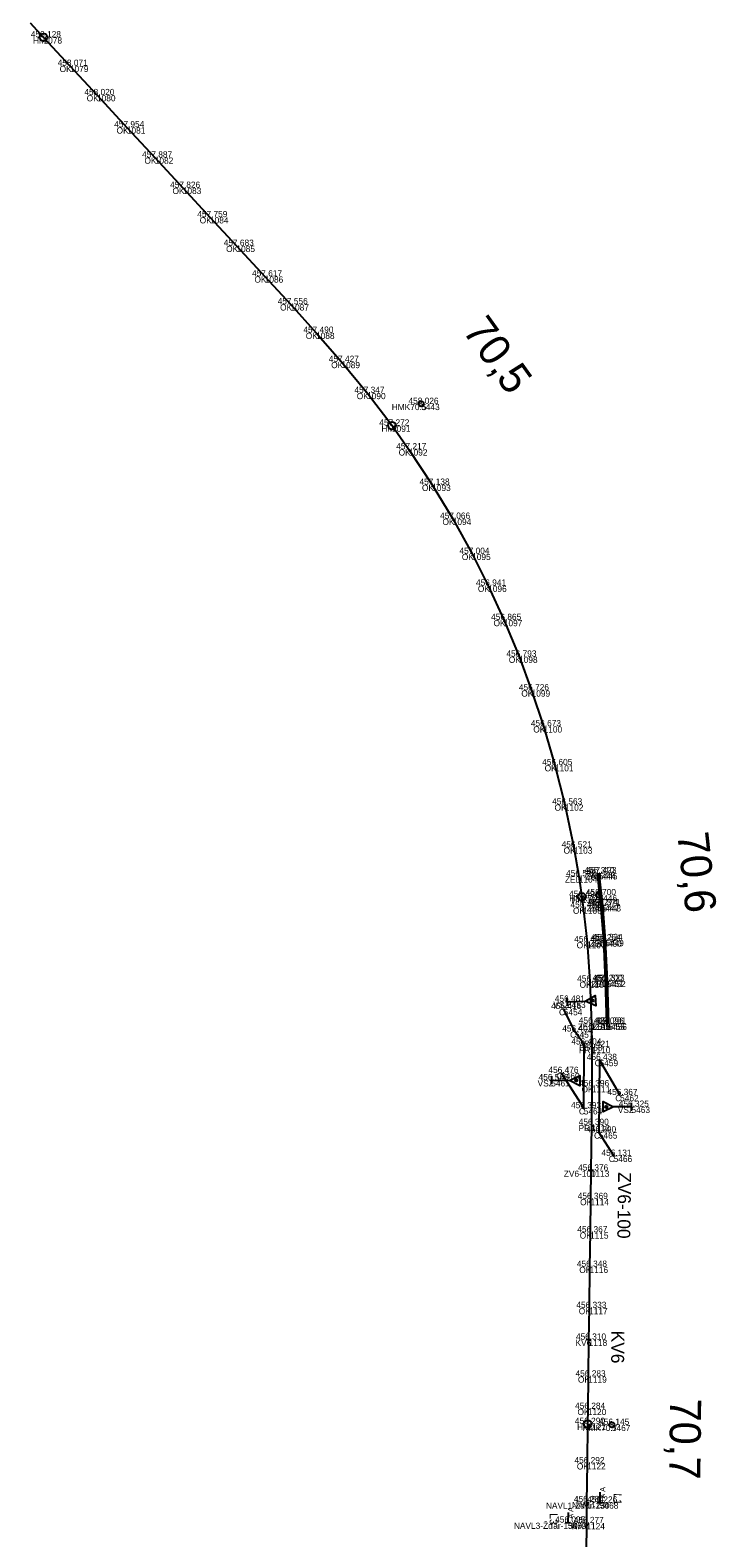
# Model space of a CAD drawing. Extents: x -621782 to -610392, y -1141853 to -1122321.
# Drawn here: x -621070.5 to -620938.2, y -1127142.3 to -1126851.5 of the extents above; entities that cross this region are included whole.
import ezdxf

# ---------------------------------------------------------------- set-up
doc = ezdxf.new("R2010")
doc.units = 0
for name, color, linetype in [('Vrstva 1', 7, 'Continuous'), ('Vrstva 13', 7, 'Continuous'), ('Vrstva 17', 7, 'Continuous'), ('Vrstva 2', 7, 'Continuous'), ('Vrstva 4', 7, 'Continuous'), ('Vrstva 51', 7, 'Continuous'), ('Vrstva 6', 7, 'Continuous'), ('Vrstva 60', 7, 'Continuous'), ('Vrstva 61', 7, 'Continuous'), ('Vrstva 62', 7, 'Continuous'), ('Vrstva 7', 7, 'Continuous')]:
    doc.layers.add(name, color=color, linetype=linetype)

msp = doc.modelspace()

# ---------------------------------------------------------------- linework, layer by layer
at = {"layer": 'Vrstva 1'}
msp.add_lwpolyline([(-621070.48, -1126850.1), (-621067.91, -1126852.88), (-621062.83, -1126858.37), (-621057.6, -1126864.02), (-621051.85, -1126870.24), (-621046.47, -1126876.06), (-621041.07, -1126881.9), (-621035.83, -1126887.57), (-621030.73, -1126893.09), (-621025.28, -1126898.99), (-621020.33, -1126904.37), (-621015.39, -1126909.86), (-621010.49, -1126915.49), (-621005.55, -1126921.47), (-621000.75, -1126927.77), (-620997.48, -1126932.35), (-620993, -1126939.18), (-620989.04, -1126945.74), (-620985.31, -1126952.51), (-620982.22, -1126958.65), (-620979.2, -1126965.27), (-620976.26, -1126972.34), (-620973.84, -1126978.85), (-620971.53, -1126985.78), (-620969.34, -1126993.26), (-620967.43, -1127000.86), (-620965.7, -1127009.15), (-620964.75, -1127014.72), (-620964.16, -1127018.68), (-620963.89, -1127020.75), (-620963.17, -1127027.41), (-620962.62, -1127035.03), (-620962.3, -1127043.11), (-620962.23, -1127047.63), (-620962.23, -1127055.2), (-620962.32, -1127062.67), (-620962.43, -1127071.48), (-620962.51, -1127076.96), (-620962.59, -1127083.4), (-620962.67, -1127090.04), (-620962.77, -1127097.99), (-620962.85, -1127104.1), (-620962.93, -1127111.2), (-620963.02, -1127117.44), (-620963.05, -1127120.35), (-620963.14, -1127127.94), (-620963.24, -1127135.43), (-620963.29, -1127139.48), (-620963.35, -1127145.19)], dxfattribs=at)
at = {"layer": 'Vrstva 13'}
msp.add_lwpolyline([(-620961.21, -1127014.13), (-620960.55, -1127020.26), (-620960.02, -1127027.08), (-620959.65, -1127034.88), (-620959.44, -1127043.15)], dxfattribs=at)
at = {"layer": 'Vrstva 17'}
msp.add_lwpolyline([(-620960.86, -1127014.1), (-620960.19, -1127020.28), (-620959.65, -1127027.01), (-620959.28, -1127034.89), (-620959.05, -1127043.14)], dxfattribs=at)
at = {"layer": 'Vrstva 2'}
for p, q in [((-620961.93, -1127071.49), (-620962.93, -1127071.47)), ((-620962.35, -1127104.1), (-620963.35, -1127104.09))]:
    msp.add_line(p, q, dxfattribs=at)
at = {"layer": 'Vrstva 4'}
for p, q in [((-620967.04, -1127038.12), (-620966.98, -1127039.68)), ((-620962.35, -1127038.52), (-620961.99, -1127038.85)), ((-620970.04, -1127053.27), (-620970.06, -1127054.82)), ((-620965.38, -1127053.9), (-620965.04, -1127054.25)), ((-620959.26, -1127059.37), (-620959.6, -1127059.03)), ((-620954.6, -1127059.95), (-620954.59, -1127058.4))]:
    msp.add_line(p, q, dxfattribs=at)
for points in [[(-620967.01, -1127038.9), (-620963.53, -1127038.77), (-620961.57, -1127037.71), (-620961.49, -1127039.7), (-620963.53, -1127038.77)], [(-620962.23, -1127047.63), (-620962.23, -1127055.2), (-620962.32, -1127062.67)], [(-620970.05, -1127054.05), (-620966.57, -1127054.09), (-620964.55, -1127053.12), (-620964.57, -1127055.12), (-620966.57, -1127054.09)], [(-620954.59, -1127059.17), (-620958.07, -1127059.17), (-620960.08, -1127060.16), (-620960.08, -1127058.16), (-620958.07, -1127059.17)]]:
    msp.add_lwpolyline(points, dxfattribs=at)
for centre in [(-620962.17, -1127038.69), (-620965.21, -1127054.07), (-620959.43, -1127059.2)]:
    msp.add_circle(centre, 0.248, dxfattribs=at)
at = {"layer": 'Vrstva 51'}
for points in [[(-620968.16, -1127052.65), (-620963.8, -1127059.45), (-620963.74, -1127047.16), (-620965.49, -1127044.65), (-620967.64, -1127040.32)], [(-620956.78, -1127056.91), (-620960.75, -1127050.14), (-620960.89, -1127064.12), (-620958.03, -1127068.63)]]:
    msp.add_lwpolyline(points, dxfattribs=at)
at = {"layer": 'Vrstva 6'}
for p, q in [((-620960.67, -1127133.53), (-620960.69, -1127135.51)), ((-620961.19, -1127135.5), (-620960.19, -1127135.51)), ((-620967.35, -1127139.39), (-620966.35, -1127139.4)), ((-620966.83, -1127137.41), (-620966.85, -1127139.39))]:
    msp.add_line(p, q, dxfattribs=at)
at = {"layer": 'Vrstva 60'}
for p, q in [((-621067.91, -1126852.88), (-621067.91, -1126852.88)), ((-621062.83, -1126858.37), (-621062.83, -1126858.37)), ((-621057.6, -1126864.02), (-621057.6, -1126864.02)), ((-621051.85, -1126870.24), (-621051.85, -1126870.24)), ((-621046.47, -1126876.06), (-621046.47, -1126876.06)), ((-621041.07, -1126881.9), (-621041.07, -1126881.9)), ((-621035.83, -1126887.57), (-621035.83, -1126887.57)), ((-621030.73, -1126893.09), (-621030.73, -1126893.09)), ((-621025.28, -1126898.99), (-621025.28, -1126898.99)), ((-621020.33, -1126904.37), (-621020.33, -1126904.37)), ((-621015.39, -1126909.86), (-621015.39, -1126909.86)), ((-621010.49, -1126915.49), (-621010.49, -1126915.49)), ((-621005.55, -1126921.47), (-621005.55, -1126921.47)), ((-620995.13, -1126923.58), (-620995.13, -1126923.58)), ((-621000.75, -1126927.77), (-621000.75, -1126927.77)), ((-620997.48, -1126932.35), (-620997.48, -1126932.35)), ((-620993, -1126939.18), (-620993, -1126939.18)), ((-620989.04, -1126945.74), (-620989.04, -1126945.74)), ((-620985.31, -1126952.51), (-620985.31, -1126952.51)), ((-620982.22, -1126958.65), (-620982.22, -1126958.65)), ((-620979.2, -1126965.27), (-620979.2, -1126965.27)), ((-620976.26, -1126972.34), (-620976.26, -1126972.34)), ((-620973.84, -1126978.85), (-620973.84, -1126978.85)), ((-620971.53, -1126985.78), (-620971.53, -1126985.78)), ((-620969.34, -1126993.26), (-620969.34, -1126993.26)), ((-620967.43, -1127000.86), (-620967.43, -1127000.86)), ((-620965.7, -1127009.15), (-620965.7, -1127009.15)), ((-620961.21, -1127014.13), (-620961.21, -1127014.13)), ((-620960.86, -1127014.1), (-620960.86, -1127014.1)), ((-620964.75, -1127014.72), (-620964.75, -1127014.72)), ((-620964.16, -1127018.68), (-620964.16, -1127018.68)), ((-620960.94, -1127018.35), (-620960.94, -1127018.35)), ((-620960.55, -1127020.26), (-620960.55, -1127020.26)), ((-620960.19, -1127020.28), (-620960.19, -1127020.28)), ((-620963.89, -1127020.75), (-620963.89, -1127020.75)), ((-620963.17, -1127027.41), (-620963.17, -1127027.41)), ((-620960.02, -1127027.08), (-620960.02, -1127027.08)), ((-620959.65, -1127027.01), (-620959.65, -1127027.01)), ((-620959.65, -1127034.88), (-620959.65, -1127034.88)), ((-620959.28, -1127034.89), (-620959.28, -1127034.89)), ((-620962.62, -1127035.03), (-620962.62, -1127035.03)), ((-620967.64, -1127040.32), (-620967.64, -1127040.32)), ((-620967.01, -1127038.9), (-620967.01, -1127038.9)), ((-620962.3, -1127043.11), (-620962.3, -1127043.11)), ((-620959.44, -1127043.15), (-620959.44, -1127043.15)), ((-620959.05, -1127043.14), (-620959.05, -1127043.14)), ((-620965.49, -1127044.65), (-620965.49, -1127044.65)), ((-620963.74, -1127047.16), (-620963.74, -1127047.16)), ((-620962.23, -1127047.63), (-620962.23, -1127047.63)), ((-620960.75, -1127050.14), (-620960.75, -1127050.14)), ((-620970.05, -1127054.05), (-620970.05, -1127054.05)), ((-620968.16, -1127052.65), (-620968.16, -1127052.65)), ((-620962.23, -1127055.2), (-620962.23, -1127055.2)), ((-620956.78, -1127056.91), (-620956.78, -1127056.91)), ((-620963.8, -1127059.45), (-620963.8, -1127059.45)), ((-620954.59, -1127059.17), (-620954.59, -1127059.17)), ((-620962.32, -1127062.67), (-620962.32, -1127062.67)), ((-620960.89, -1127064.12), (-620960.89, -1127064.12)), ((-620958.03, -1127068.63), (-620958.03, -1127068.63)), ((-620962.43, -1127071.48), (-620962.43, -1127071.48)), ((-620962.51, -1127076.96), (-620962.51, -1127076.96)), ((-620962.59, -1127083.4), (-620962.59, -1127083.4)), ((-620962.67, -1127090.04), (-620962.67, -1127090.04)), ((-620962.77, -1127097.99), (-620962.77, -1127097.99)), ((-620962.85, -1127104.1), (-620962.85, -1127104.1)), ((-620962.93, -1127111.2), (-620962.93, -1127111.2)), ((-620963.02, -1127117.44), (-620963.02, -1127117.44)), ((-620963.05, -1127120.35), (-620963.05, -1127120.35)), ((-620958.37, -1127120.53), (-620958.37, -1127120.53)), ((-620963.14, -1127127.94), (-620963.14, -1127127.94)), ((-620963.24, -1127135.43), (-620963.24, -1127135.43)), ((-620960.69, -1127135.51), (-620960.69, -1127135.51)), ((-620966.85, -1127139.39), (-620966.85, -1127139.39)), ((-620963.29, -1127139.48), (-620963.29, -1127139.48))]:
    msp.add_line(p, q, dxfattribs=at)
at = {"layer": 'Vrstva 7'}
for p, q in [((-620995.16, -1126923.54), (-620995.1, -1126923.62)), ((-620960.94, -1127018.3), (-620960.93, -1127018.4)), ((-620958.37, -1127120.48), (-620958.37, -1127120.57))]:
    msp.add_line(p, q, dxfattribs=at)
for centre, radius in [((-621067.91, -1126852.88), 0.75), ((-620995.13, -1126923.58), 0.5), ((-621000.75, -1126927.77), 0.75), ((-620964.16, -1127018.68), 0.75), ((-620960.94, -1127018.35), 0.5), ((-620963.05, -1127120.35), 0.75), ((-620958.37, -1127120.53), 0.5)]:
    msp.add_circle(centre, radius, dxfattribs=at)

# ---------------------------------------------------------------- texts
at = {"layer": 'Vrstva 2'}
for s, rotation, p in [('ZV6-100', 269.1845, (-620957.16, -1127071.76)), ('KV6', 269.3062, (-620958.45, -1127102.35))]:
    msp.add_text(s, height=2.5, rotation=rotation, dxfattribs=at).set_placement(p)
at = {"layer": 'Vrstva 6'}
for s, height, rotation, p in [('  A A ', 1, 89.3485, (-620959.69, -1127135.52)), ('  A A ', 1, 89.3184, (-620965.85, -1127139.4)), ('L1', 1.5, 269.3485, (-620958, -1127133.73)), ('L3', 1.5, 269.3184, (-620970.34, -1127137.57))]:
    msp.add_text(s, height=height, rotation=rotation, dxfattribs=at).set_placement(p)
at = {"layer": 'Vrstva 60'}
for s, p in [('1078', (-621067.91, -1126854.07)), ('1079', (-621062.83, -1126859.57)), ('1080', (-621057.6, -1126865.22)), ('1081', (-621051.85, -1126871.44)), ('1082', (-621046.47, -1126877.26)), ('1083', (-621041.07, -1126883.1)), ('1084', (-621035.83, -1126888.77)), ('1085', (-621030.73, -1126894.29)), ('1086', (-621025.28, -1126900.19)), ('1087', (-621020.33, -1126905.57)), ('1088', (-621015.39, -1126911.06)), ('1089', (-621010.49, -1126916.69)), ('1090', (-621005.55, -1126922.67)), ('5443', (-620995.13, -1126924.78)), ('1091', (-621000.75, -1126928.97)), ('1092', (-620997.48, -1126933.55)), ('1093', (-620993, -1126940.38)), ('1094', (-620989.04, -1126946.94)), ('1095', (-620985.31, -1126953.71)), ('1096', (-620982.22, -1126959.85)), ('1097', (-620979.2, -1126966.47)), ('1098', (-620976.26, -1126973.54)), ('1099', (-620973.84, -1126980.05)), ('1100', (-620971.53, -1126986.98)), ('1101', (-620969.34, -1126994.46)), ('1102', (-620967.43, -1127002.06)), ('1103', (-620965.7, -1127010.35)), ('5444', (-620961.21, -1127015.33)), ('5445', (-620960.86, -1127015.3)), ('1104', (-620964.75, -1127015.92)), ('1105', (-620964.16, -1127019.88)), ('5446', (-620960.94, -1127019.55)), ('5447', (-620960.55, -1127021.46)), ('5448', (-620960.19, -1127021.49)), ('1106', (-620963.89, -1127021.95)), ('1107', (-620963.17, -1127028.61)), ('5450', (-620960.02, -1127028.28)), ('5449', (-620959.65, -1127028.21)), ('5451', (-620959.65, -1127036.08)), ('5452', (-620959.28, -1127036.09)), ('1108', (-620962.62, -1127036.23)), ('5454', (-620967.64, -1127041.52)), ('5453', (-620967.01, -1127040.1)), ('1109', (-620962.3, -1127044.31)), ('5455', (-620959.44, -1127044.35)), ('5456', (-620959.05, -1127044.34)), ('5457', (-620965.49, -1127045.85)), ('5458', (-620963.74, -1127048.36)), ('1110', (-620962.23, -1127048.83)), ('5459', (-620960.75, -1127051.34)), ('5461', (-620970.05, -1127055.25)), ('5460', (-620968.16, -1127053.84)), ('1111', (-620962.23, -1127056.4)), ('5462', (-620956.78, -1127058.11)), ('5464', (-620963.8, -1127060.65)), ('5463', (-620954.59, -1127060.37)), ('1112', (-620962.32, -1127063.87)), ('5465', (-620960.89, -1127065.32)), ('5466', (-620958.03, -1127069.83)), ('1113', (-620962.43, -1127072.68)), ('1114', (-620962.51, -1127078.16)), ('1115', (-620962.59, -1127084.6)), ('1116', (-620962.67, -1127091.24)), ('1117', (-620962.77, -1127099.19)), ('1118', (-620962.85, -1127105.3)), ('1119', (-620962.93, -1127112.4)), ('1120', (-620963.02, -1127118.64)), ('1121', (-620963.05, -1127121.55)), ('5467', (-620958.37, -1127121.73)), ('1122', (-620963.14, -1127129.14)), ('1123', (-620963.24, -1127136.63)), ('5468', (-620960.69, -1127136.71)), ('5469', (-620966.85, -1127140.59)), ('1124', (-620963.29, -1127140.68))]:
    msp.add_text(s, height=1.2, dxfattribs=at).set_placement(p)
at = {"layer": 'Vrstva 61'}
for s, p in [('458.128', (-621070.36, -1126852.88)), ('458.071', (-621065.19, -1126858.37)), ('458.020', (-621060.05, -1126864.02)), ('457.954', (-621054.3, -1126870.24)), ('457.887', (-621048.92, -1126876.06)), ('457.826', (-621043.52, -1126881.9)), ('457.759', (-621038.28, -1126887.57)), ('457.683', (-621033.19, -1126893.09)), ('457.617', (-621027.73, -1126898.99)), ('457.556', (-621022.79, -1126904.37)), ('457.490', (-621017.84, -1126909.86)), ('457.427', (-621012.94, -1126915.49)), ('457.347', (-621008, -1126921.47)), ('458.026', (-620997.58, -1126923.58)), ('457.272', (-621003.2, -1126927.77)), ('457.217', (-620999.94, -1126932.35)), ('457.138', (-620995.45, -1126939.18)), ('457.066', (-620991.49, -1126945.74)), ('457.004', (-620987.76, -1126952.51)), ('456.941', (-620984.57, -1126958.65)), ('456.865', (-620981.65, -1126965.27)), ('456.793', (-620978.71, -1126972.34)), ('456.726', (-620976.3, -1126978.85)), ('456.673', (-620973.98, -1126985.78)), ('456.605', (-620971.8, -1126993.26)), ('456.563', (-620969.89, -1127000.86)), ('456.521', (-620968.06, -1127009.15)), ('456.508', (-620967.2, -1127014.72)), ('456.310', (-620963.66, -1127014.13)), ('457.423', (-620963.31, -1127014.1)), ('456.494', (-620966.61, -1127018.68)), ('456.700', (-620963.39, -1127018.35)), ('456.492', (-620966.34, -1127020.75)), ('456.274', (-620963, -1127020.26)), ('457.371', (-620962.55, -1127020.28)), ('456.475', (-620965.63, -1127027.41)), ('456.254', (-620962.47, -1127027.08)), ('457.334', (-620962.1, -1127027.01)), ('456.452', (-620965.06, -1127035.03)), ('456.200', (-620962.1, -1127034.88)), ('457.323', (-620961.73, -1127034.89)), ('456.481', (-620969.37, -1127038.9)), ('456.416', (-620970.09, -1127040.32)), ('456.402', (-620967.94, -1127044.65)), ('456.424', (-620964.75, -1127043.11)), ('456.096', (-620961.89, -1127043.15)), ('457.201', (-620961.41, -1127043.14)), ('456.404', (-620966.19, -1127047.16)), ('456.421', (-620964.59, -1127047.63)), ('456.438', (-620963.21, -1127050.14)), ('456.476', (-620970.61, -1127052.65)), ('456.565', (-620972.5, -1127054.05)), ('456.396', (-620964.69, -1127055.2)), ('456.393', (-620966.25, -1127059.45)), ('456.367', (-620959.23, -1127056.91)), ('456.325', (-620957.05, -1127059.17)), ('456.390', (-620964.77, -1127062.67)), ('456.390', (-620963.34, -1127064.12)), ('456.131', (-620960.39, -1127068.63)), ('456.376', (-620964.88, -1127071.48)), ('456.369', (-620964.96, -1127076.96)), ('456.367', (-620965.04, -1127083.4)), ('456.348', (-620965.12, -1127090.04)), ('456.333', (-620965.23, -1127097.99)), ('456.310', (-620965.3, -1127104.1)), ('456.283', (-620965.38, -1127111.2)), ('456.284', (-620965.47, -1127117.44)), ('456.290', (-620965.5, -1127120.35)), ('456.145', (-620960.83, -1127120.53)), ('456.292', (-620965.59, -1127127.94)), ('456.284', (-620965.69, -1127135.43)), ('456.226', (-620963.14, -1127135.51)), ('456.095', (-620969.31, -1127139.39)), ('456.277', (-620965.74, -1127139.48))]:
    msp.add_text(s, height=1.2, dxfattribs=at).set_placement(p)
at = {"layer": 'Vrstva 62'}
for s, p in [('HM', (-621069.94, -1126854.07)), ('OK', (-621064.81, -1126859.57)), ('OK', (-621059.59, -1126865.22)), ('OK', (-621053.83, -1126871.44)), ('OK', (-621048.46, -1126877.26)), ('OK', (-621043.05, -1126883.1)), ('OK', (-621037.81, -1126888.77)), ('OK', (-621032.72, -1126894.29)), ('OK', (-621027.26, -1126900.19)), ('OK', (-621022.32, -1126905.57)), ('OK', (-621017.37, -1126911.06)), ('OK', (-621012.47, -1126916.69)), ('OK', (-621007.54, -1126922.67)), ('HMK70.5', (-621000.8, -1126924.78)), ('HM', (-621002.79, -1126928.97)), ('OK', (-620999.47, -1126933.55)), ('OK', (-620994.98, -1126940.38)), ('OK', (-620991.02, -1126946.94)), ('OK', (-620987.29, -1126953.71)), ('OK', (-620984.2, -1126959.85)), ('OK', (-620981.18, -1126966.47)), ('OK', (-620978.24, -1126973.54)), ('OK', (-620975.83, -1126980.05)), ('OK', (-620973.52, -1126986.98)), ('OK', (-620971.33, -1126994.46)), ('OK', (-620969.42, -1127002.06)), ('OK', (-620967.68, -1127010.35)), ('Zed', (-620963.48, -1127015.33)), ('ZAB', (-620963.46, -1127015.3)), ('ZED', (-620967.42, -1127015.92)), ('HMK70.6', (-620966.6, -1127019.55)), ('HM', (-620966.19, -1127019.88)), ('ZED', (-620963.22, -1127021.46)), ('ZAB', (-620962.79, -1127021.49)), ('OK', (-620965.87, -1127021.95)), ('OK', (-620965.16, -1127028.61)), ('ZED', (-620962.69, -1127028.28)), ('ZAB', (-620962.25, -1127028.21)), ('ZED', (-620962.32, -1127036.08)), ('ZAB', (-620961.88, -1127036.09)), ('OK', (-620964.6, -1127036.23)), ('VSZ', (-620969.65, -1127040.1)), ('C', (-620968.57, -1127041.52)), ('ZED', (-620964.98, -1127044.31)), ('ZED', (-620962.11, -1127044.35)), ('ZAB', (-620961.65, -1127044.34)), ('C', (-620966.43, -1127045.85)), ('C', (-620964.67, -1127048.36)), ('PRJ', (-620964.72, -1127048.83)), ('C', (-620961.69, -1127051.34)), ('VSZ', (-620972.69, -1127055.25)), ('C', (-620969.1, -1127053.84)), ('OK', (-620964.22, -1127056.4)), ('C', (-620957.72, -1127058.11)), ('C', (-620964.73, -1127060.65)), ('VSZ', (-620957.23, -1127060.37)), ('PRJ', (-620964.8, -1127063.87)), ('C', (-620961.82, -1127065.32)), ('C', (-620958.97, -1127069.83)), ('ZV6-100', (-620967.64, -1127072.68)), ('OK', (-620964.49, -1127078.16)), ('OK', (-620964.57, -1127084.6)), ('OK', (-620964.66, -1127091.24)), ('OK', (-620964.76, -1127099.19)), ('KV6', (-620965.38, -1127105.3)), ('OK', (-620964.92, -1127112.4)), ('OK', (-620965, -1127118.64)), ('HM', (-620965.09, -1127121.55)), ('HMK70.7', (-620964.03, -1127121.73)), ('OK', (-620965.13, -1127129.14)), ('NAVL1-Žďár-130', (-620971.09, -1127136.71)), ('NAV', (-620966.05, -1127136.63)), ('NAVL3-Žďár-130', (-620977.26, -1127140.59)), ('NAV', (-620966.1, -1127140.68))]:
    msp.add_text(s, height=1.2, dxfattribs=at).set_placement(p)
at = {"layer": 'Vrstva 7'}
for s, rotation, p in [('70,5', 305.5116, (-620987.31, -1126909.46)), ('70,6', 276.1504, (-620945.79, -1127006.46)), ('70,7', 269.3129, (-620947.15, -1127115.41))]:
    msp.add_text(s, height=6, rotation=rotation, dxfattribs=at).set_placement(p)

doc.saveas('drawing.dxf')
